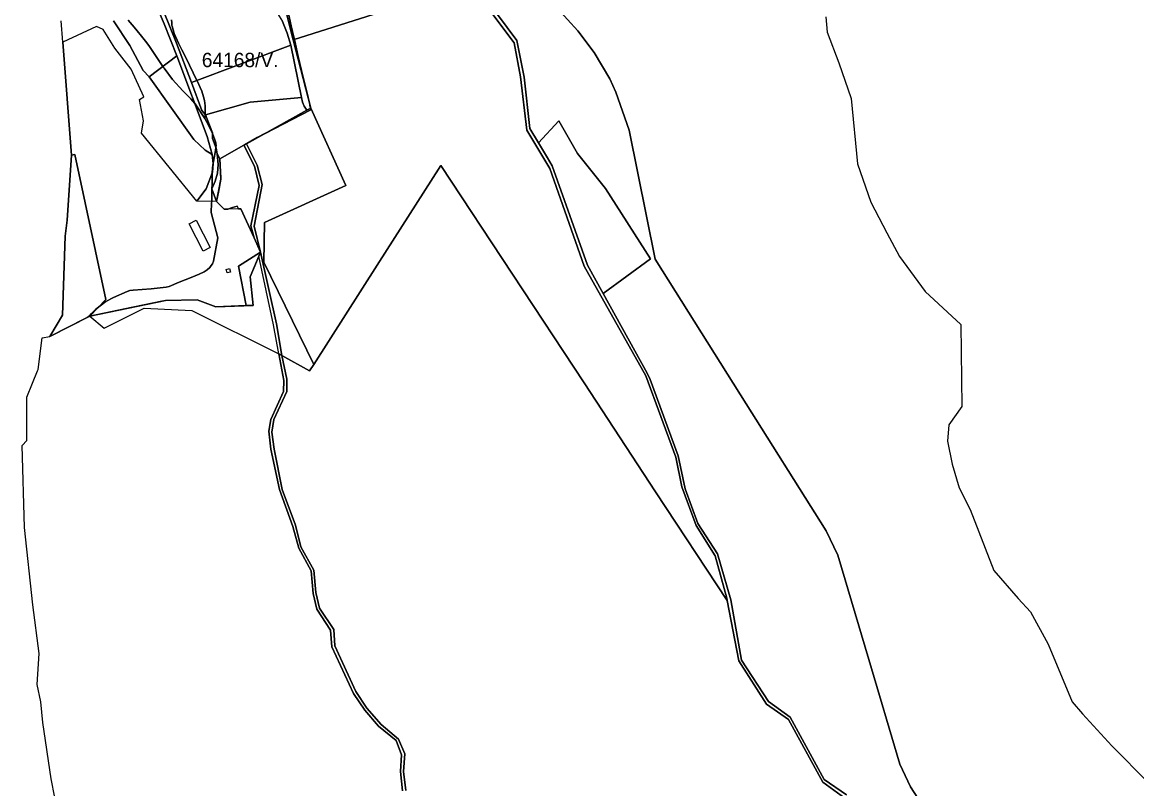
# Model space of a CAD drawing. Extents: x -521939 to -516426, y -1197857 to -1189551.
# Drawn here: x -518761 to -517594, y -1195785 to -1194982 of the extents above; entities that cross this region are included whole.
import ezdxf

# ---------------------------------------------------------------- set-up
doc = ezdxf.new("R2010")
doc.units = 0
for name, color, linetype in [('95610013', 7, 'Continuous'), ('95620013', 7, 'Continuous'), ('95640013', 7, 'Continuous'), ('95660013', 7, 'Continuous')]:
    doc.layers.add(name, color=color, linetype=linetype)

msp = doc.modelspace()

# ---------------------------------------------------------------- linework, layer by layer
at = {"layer": '95610013'}
for points in [[(-518612.73, -1194971.22), (-518551.19, -1194925.86), (-518520.66, -1194944.85), (-518503.52, -1194959.79), (-518495.28, -1194970.1), (-518488.5, -1194981.42), (-518483.3, -1194993.56), (-518479.79, -1195006.28), (-518583.67, -1195045.33), (-518599.24, -1195003.9)], [(-518479.79, -1195006.28), (-518468.55, -1195061.01), (-518522.17, -1195065.75), (-518568.86, -1195079.07), (-518572.72, -1195074.48), (-518583.67, -1195045.33)], [(-518599.15, -1195017.18), (-518567.19, -1195102), (-518561.85, -1195120.59), (-518569.49, -1195116.16), (-518581.19, -1195104.89), (-518627.9, -1195039.34)]]:
    msp.add_lwpolyline(points, close=True, dxfattribs=at)
for points in [[(-518664.08, -1195009.33), (-518676.07, -1194989.56), (-518683.25, -1194986.41), (-518718.38, -1195002.82)], [(-518718.38, -1195002.82), (-518709.39, -1195121.23)], [(-518638.26, -1195062.96), (-518633.66, -1195060.2), (-518646.72, -1195031.42), (-518664.08, -1195009.33)], [(-518633.95, -1195085.34), (-518638.26, -1195062.96)], [(-518636.1, -1195098.41), (-518633.95, -1195085.34)], [(-518577.92, -1195169.54), (-518636.1, -1195098.41)], [(-518709.39, -1195121.23), (-518705.84, -1195120.86)], [(-518705.84, -1195120.86), (-518673.48, -1195272.59), (-518690.03, -1195290)], [(-518557.33, -1195169.83), (-518577.92, -1195169.54)], [(-518518.2, -1195207.89), (-518532.16, -1195177.68), (-518549.4, -1195178.09), (-518557.33, -1195169.83)], [(-518578.9, -1195189.46), (-518563.97, -1195218.15), (-518571.3, -1195222), (-518586.21, -1195193.27)], [(-518586.21, -1195193.27), (-518578.9, -1195189.46)], [(-518511.27, -1195222.88), (-518518.2, -1195207.89)], [(-518534.54, -1195237.63), (-518511.27, -1195222.88)], [(-518547.43, -1195241.34), (-518543.93, -1195240.33), (-518542.94, -1195243.86), (-518546.46, -1195244.84)], [(-518546.46, -1195244.84), (-518547.43, -1195241.34)], [(-518526.44, -1195279.07), (-518534.54, -1195237.63)], [(-518690.03, -1195290), (-518610.94, -1195273.71), (-518577.83, -1195273)], [(-518577.83, -1195273), (-518558.14, -1195280.21), (-518526.44, -1195279.07)]]:
    msp.add_lwpolyline(points, dxfattribs=at)
at = {"layer": '95620013'}
for points in [[(-518477.04, -1195000.54), (-518484.79, -1194970.06), (-518513.79, -1194941.58), (-518572.38, -1194906.86), (-518586.43, -1194895.87), (-518625.17, -1194805.96), (-518626.13, -1194801.22), (-518615.19, -1194776.18), (-518588.67, -1194800), (-518568.59, -1194820.97), (-518540.54, -1194837.64), (-518520.62, -1194853.23), (-518507.34, -1194830.62), (-518479.49, -1194844.01), (-518465.35, -1194851.3), (-518442.17, -1194859), (-518428.24, -1194864.28), (-518400.82, -1194885.57), (-518302.06, -1194944.78)], [(-518511.27, -1195222.88), (-518518.19, -1195195.9), (-518509.49, -1195152.1), (-518514.93, -1195132.02), (-518526.18, -1195109.58), (-518462.79, -1195074.28), (-518458.85, -1195072.09), (-518422.19, -1195153.31), (-518507.32, -1195192.11), (-518507.9, -1195233.52), (-518455.62, -1195340.79), (-518459.94, -1195347.56), (-518489.13, -1195331.28), (-518494.68, -1195298.25)], [(-518169, -1195236.77), (-518205.88, -1195132.49), (-518210.84, -1195124.15), (-518220.27, -1195108.55), (-518198.96, -1195085.5), (-518179.28, -1195119.8), (-518150.08, -1195156.42), (-518103.1, -1195229.89), (-518152.55, -1195266.5)], [(-518549.4, -1195178.09), (-518557.33, -1195169.83), (-518553.05, -1195146.52), (-518553.98, -1195125.07), (-518528.8, -1195111.04), (-518517.78, -1195132.75), (-518512.67, -1195153.14), (-518521.52, -1195195.52), (-518518.2, -1195207.89), (-518532.16, -1195177.68)], [(-518492.07, -1195329.64), (-518497.86, -1195299.13), (-518513.12, -1195227.2), (-518511.27, -1195222.88), (-518494.68, -1195298.25), (-518489.13, -1195331.28)]]:
    msp.add_lwpolyline(points, close=True, dxfattribs=at)
for points in [[(-518277.38, -1194961.25), (-518245.58, -1195003.83), (-518239.05, -1195039.28), (-518232.28, -1195095.17), (-518208.33, -1195135.21), (-518172.54, -1195237.68), (-518107.85, -1195352.72), (-518076.29, -1195438.01), (-518070.24, -1195468.86), (-518055.13, -1195509.5), (-518035.17, -1195541.44), (-518022.96, -1195585.48), (-518022.49, -1195587.97), (-518097.53, -1195474.05), (-518172.57, -1195360.13), (-518247.61, -1195246.21), (-518322.65, -1195132.29), (-518389.14, -1195236.54), (-518455.62, -1195340.79), (-518507.9, -1195233.52), (-518507.32, -1195192.11), (-518422.19, -1195153.31), (-518458.85, -1195072.09), (-518477.04, -1195000.54), (-518302.06, -1194944.78)], [(-517897.53, -1195791.8), (-517920.87, -1195775.71), (-517956.78, -1195710.39), (-517979.28, -1195694.05), (-518007.69, -1195650.5), (-518018.82, -1195587.36), (-518032.6, -1195539.21), (-518053.4, -1195507.39), (-518066.46, -1195471.1), (-518073.84, -1195436.5), (-518103.22, -1195356.54), (-518106.36, -1195350), (-518152.55, -1195266.5), (-518103.1, -1195229.89), (-518150.08, -1195156.42), (-518179.28, -1195119.8), (-518198.96, -1195085.5), (-518220.27, -1195108.55), (-518229.34, -1195093.54), (-518235.27, -1195039.83), (-518242.88, -1195001.36), (-518274.2, -1194958.76)], [(-518200.55, -1194967.23), (-518179.17, -1194990.94), (-518161.76, -1195013.8), (-518145.64, -1195041.48), (-518139.37, -1195055.41), (-518125.34, -1195095.33), (-518098.11, -1195230.42), (-518008.6, -1195372.71), (-517919.1, -1195515.01), (-517906.62, -1195540.42), (-517874.16, -1195650.02), (-517841.71, -1195759.62), (-517830.56, -1195783.46), (-517733.42, -1195933.26), (-517671.34, -1196044.27), (-517550.36, -1196112.6)], [(-517550.36, -1196112.6), (-517671.34, -1196044.27), (-517733.42, -1195933.26), (-517830.56, -1195783.46), (-517841.71, -1195759.62), (-517874.16, -1195650.02), (-517906.62, -1195540.42), (-517919.1, -1195515.01), (-518008.6, -1195372.71), (-518098.11, -1195230.42), (-518125.34, -1195095.33), (-518139.37, -1195055.41), (-518145.64, -1195041.48), (-518161.76, -1195013.8), (-518179.17, -1194990.94), (-518200.55, -1194967.23)], [(-517919.16, -1194976.41), (-517918.02, -1194992.59), (-517905.77, -1195024.59), (-517892.85, -1195062.16), (-517886.13, -1195130.55), (-517872.07, -1195170.61), (-517855.27, -1195202.9), (-517841.99, -1195227.55), (-517815.27, -1195264.33), (-517777.74, -1195299), (-517776.69, -1195384.65), (-517790.61, -1195404.02), (-517791.97, -1195421.06), (-517786.92, -1195445.13), (-517779.75, -1195470.04), (-517768.13, -1195492.77), (-517743.18, -1195556.56), (-517718.01, -1195585.89), (-517705.09, -1195599.86), (-517686.33, -1195633.83), (-517661.21, -1195694.16), (-517650.43, -1195706.76), (-517619.7, -1195740.35), (-517580.93, -1195779.39)], [(-518709.39, -1195121.23), (-518713.87, -1195189.36)], [(-518690.03, -1195290), (-518673.48, -1195272.59), (-518705.84, -1195120.86), (-518709.39, -1195121.23)], [(-518359.34, -1195787.34), (-518361.52, -1195767.14), (-518360.06, -1195748.63), (-518366.96, -1195733.39), (-518384.97, -1195718.15), (-518400.09, -1195700.97), (-518411.58, -1195683.31), (-518433.46, -1195635.76), (-518434.43, -1195618.46), (-518449.55, -1195596.21), (-518453.54, -1195579.75), (-518455.59, -1195556.28), (-518469.14, -1195531.73), (-518474.58, -1195509.22), (-518488.85, -1195471.72), (-518497.07, -1195429.38), (-518499.49, -1195411.6), (-518497.55, -1195398.29), (-518483.65, -1195369.14), (-518483.89, -1195356.31), (-518489.13, -1195331.28), (-518459.94, -1195347.56), (-518455.62, -1195340.79), (-518389.14, -1195236.54), (-518322.65, -1195132.29), (-518247.61, -1195246.21), (-518172.57, -1195360.13), (-518097.53, -1195474.05), (-518022.49, -1195587.97), (-518010.51, -1195651.29), (-517981.36, -1195696.65), (-517958.51, -1195712.86), (-517922.6, -1195778.43), (-517899.26, -1195795.12)], [(-518713.87, -1195189.36), (-518716.08, -1195206.38)], [(-518716.08, -1195206.38), (-518718.82, -1195289.08)], [(-518511.27, -1195222.88), (-518534.54, -1195237.63), (-518526.44, -1195279.07)], [(-518513.12, -1195227.2), (-518511.27, -1195222.88)], [(-518522.38, -1195248.79), (-518513.12, -1195227.2)], [(-518513.12, -1195227.2), (-518522.38, -1195248.79)], [(-518497.86, -1195299.13), (-518513.12, -1195227.2)], [(-518526.44, -1195279.07), (-518519.2, -1195278.81), (-518522.38, -1195248.79)], [(-518522.38, -1195248.79), (-518519.2, -1195278.81), (-518526.44, -1195279.07)], [(-518726.63, -1195794.44), (-518730.8, -1195775.07), (-518739.22, -1195715.86), (-518741.37, -1195694.14), (-518745.32, -1195675.95), (-518743.14, -1195643.78), (-518749.83, -1195592.65), (-518758.62, -1195511.5), (-518760.89, -1195425.68), (-518755.96, -1195420.36), (-518756, -1195391.6), (-518756.03, -1195375.1), (-518750.12, -1195360.34), (-518744.97, -1195347.47), (-518744.35, -1195345.93), (-518740.14, -1195312.89), (-518731.97, -1195311.31), (-518690.03, -1195290), (-518675.19, -1195302.83), (-518633.33, -1195281.9), (-518583.48, -1195284.08), (-518492.07, -1195329.64), (-518487, -1195357.52), (-518487.48, -1195369.14), (-518500.47, -1195398.45), (-518502.61, -1195410.75), (-518500.64, -1195429.42), (-518491.66, -1195471.79), (-518477.5, -1195510.37), (-518471.35, -1195533.39), (-518458.29, -1195557.03), (-518456.21, -1195580.74), (-518452.41, -1195597.12), (-518437.97, -1195619.03), (-518436.59, -1195636.73), (-518414.13, -1195685.4), (-518402.18, -1195703.09), (-518387.88, -1195719.82), (-518369.43, -1195734.96), (-518363.62, -1195749.69), (-518364.73, -1195767.11), (-518362.66, -1195787.64)], [(-518526.44, -1195279.07), (-518558.14, -1195280.21), (-518577.83, -1195273), (-518610.94, -1195273.71), (-518690.03, -1195290)], [(-518690.03, -1195290), (-518675.19, -1195302.83), (-518633.33, -1195281.9)], [(-518633.33, -1195281.9), (-518583.48, -1195284.08), (-518492.07, -1195329.64)], [(-518718.82, -1195289.08), (-518731.97, -1195311.31)], [(-518731.97, -1195311.31), (-518690.03, -1195290)], [(-518492.07, -1195329.64), (-518497.86, -1195299.13)], [(-518362.66, -1195787.64), (-518364.73, -1195767.11), (-518363.62, -1195749.69), (-518369.43, -1195734.96), (-518387.88, -1195719.82), (-518402.18, -1195703.09), (-518414.13, -1195685.4), (-518436.59, -1195636.73), (-518437.97, -1195619.03), (-518452.41, -1195597.12), (-518456.21, -1195580.74), (-518458.29, -1195557.03), (-518471.35, -1195533.39), (-518477.5, -1195510.37), (-518491.66, -1195471.79), (-518500.64, -1195429.42), (-518502.61, -1195410.75), (-518500.47, -1195398.45), (-518487.48, -1195369.14), (-518487, -1195357.52), (-518492.07, -1195329.64), (-518489.13, -1195331.28), (-518483.89, -1195356.31), (-518483.65, -1195369.14), (-518497.55, -1195398.29), (-518499.49, -1195411.6), (-518497.07, -1195429.38), (-518488.85, -1195471.72), (-518474.58, -1195509.22), (-518469.14, -1195531.73), (-518455.59, -1195556.28), (-518453.54, -1195579.75), (-518449.55, -1195596.21), (-518434.43, -1195618.46), (-518433.46, -1195635.76), (-518411.58, -1195683.31), (-518400.09, -1195700.97), (-518384.97, -1195718.15), (-518366.96, -1195733.39), (-518360.06, -1195748.63), (-518361.52, -1195767.14), (-518359.34, -1195787.34)]]:
    msp.add_lwpolyline(points, dxfattribs=at)
at = {"layer": '95640013'}
for points in [[(-518621.14, -1194963.55), (-518612.46, -1194983.75), (-518599.15, -1195017.18), (-518627.9, -1195039.34), (-518634.25, -1195032.5), (-518648.26, -1195006.39), (-518665.42, -1194980.49)], [(-518612.73, -1194971.22), (-518599.24, -1195003.9), (-518583.67, -1195045.33), (-518572.72, -1195074.48), (-518568.86, -1195079.07), (-518561.77, -1195097.95), (-518561.65, -1195103.95), (-518557.91, -1195113.9), (-518556.68, -1195119.84), (-518555.66, -1195131.33), (-518556.55, -1195140.1), (-518558.78, -1195148.62), (-518562.28, -1195156.71), (-518557.33, -1195169.83), (-518577.92, -1195169.54), (-518568.34, -1195156.53), (-518561.84, -1195139.14), (-518560.97, -1195129.99), (-518561.85, -1195120.59), (-518567.19, -1195102), (-518599.15, -1195017.18), (-518612.46, -1194983.75), (-518621.14, -1194963.55)], [(-517899.26, -1195795.12), (-517922.6, -1195778.43), (-517958.51, -1195712.86), (-517981.36, -1195696.65), (-518010.51, -1195651.29), (-518022.49, -1195587.97), (-518022.96, -1195585.48), (-518035.17, -1195541.44), (-518055.13, -1195509.5), (-518070.24, -1195468.86), (-518076.29, -1195438.01), (-518107.85, -1195352.72), (-518172.54, -1195237.68), (-518208.33, -1195135.21), (-518232.28, -1195095.17), (-518239.05, -1195039.28), (-518245.58, -1195003.83), (-518277.38, -1194961.25)], [(-518274.2, -1194958.76), (-518242.88, -1195001.36), (-518235.27, -1195039.83), (-518229.34, -1195093.54), (-518220.27, -1195108.55), (-518210.84, -1195124.15), (-518205.88, -1195132.49), (-518169, -1195236.77), (-518152.55, -1195266.5), (-518106.36, -1195350), (-518103.22, -1195356.54), (-518073.84, -1195436.5), (-518066.46, -1195471.1), (-518053.4, -1195507.39), (-518032.6, -1195539.21), (-518018.82, -1195587.36), (-518007.69, -1195650.5), (-517979.28, -1195694.05), (-517956.78, -1195710.39), (-517920.87, -1195775.71), (-517897.53, -1195791.8)], [(-518484.79, -1194970.06), (-518477.04, -1195000.54), (-518458.85, -1195072.09), (-518462.79, -1195074.28), (-518463.67, -1195073.15), (-518465.57, -1195070.13), (-518467.43, -1195065.76), (-518468.55, -1195061.01), (-518479.79, -1195006.28), (-518483.3, -1194993.56), (-518488.5, -1194981.42)], [(-518665.42, -1194980.49), (-518648.26, -1195006.39), (-518634.25, -1195032.5), (-518627.9, -1195039.34), (-518581.19, -1195104.89), (-518569.49, -1195116.16), (-518561.85, -1195120.59), (-518560.97, -1195129.99), (-518561.84, -1195139.14), (-518568.34, -1195156.53), (-518577.92, -1195169.54), (-518636.1, -1195098.41), (-518633.95, -1195085.34), (-518638.26, -1195062.96), (-518633.66, -1195060.2), (-518646.72, -1195031.42), (-518664.08, -1195009.33), (-518676.07, -1194989.56), (-518683.25, -1194986.41), (-518718.38, -1195002.82), (-518720.07, -1194980.61)]]:
    msp.add_lwpolyline(points, dxfattribs=at)
for points in [[(-518556.68, -1195119.84), (-518557.91, -1195113.9), (-518561.65, -1195103.95), (-518561.77, -1195097.95), (-518568.86, -1195079.07), (-518522.17, -1195065.75), (-518468.55, -1195061.01), (-518467.43, -1195065.76), (-518465.57, -1195070.13), (-518463.67, -1195073.15), (-518462.79, -1195074.28), (-518526.18, -1195109.58), (-518528.8, -1195111.04), (-518553.98, -1195125.07)], [(-518518.19, -1195195.9), (-518511.27, -1195222.88), (-518518.2, -1195207.89), (-518521.52, -1195195.52), (-518512.67, -1195153.14), (-518517.78, -1195132.75), (-518528.8, -1195111.04), (-518526.18, -1195109.58), (-518514.93, -1195132.02), (-518509.49, -1195152.1)], [(-518557.33, -1195169.83), (-518562.28, -1195156.71), (-518558.78, -1195148.62), (-518556.55, -1195140.1), (-518555.66, -1195131.33), (-518556.68, -1195119.84), (-518553.98, -1195125.07), (-518553.05, -1195146.52)], [(-518586.21, -1195193.27), (-518578.9, -1195189.46), (-518563.97, -1195218.15), (-518571.3, -1195222)], [(-518547.43, -1195241.34), (-518543.93, -1195240.33), (-518542.94, -1195243.86), (-518546.46, -1195244.84)]]:
    msp.add_lwpolyline(points, close=True, dxfattribs=at)
at = {"layer": '95660013'}
for points in [[(-518726.63, -1195794.44), (-518730.8, -1195775.07), (-518739.22, -1195715.86), (-518741.37, -1195694.14), (-518745.32, -1195675.95), (-518743.14, -1195643.78), (-518749.83, -1195592.65), (-518758.62, -1195511.5), (-518760.89, -1195425.68), (-518755.96, -1195420.36), (-518756, -1195391.6), (-518756.03, -1195375.1), (-518750.12, -1195360.34), (-518744.97, -1195347.47), (-518744.35, -1195345.93), (-518740.14, -1195312.89), (-518731.97, -1195311.31), (-518695.18, -1195292.62), (-518691.72, -1195290.85), (-518690.03, -1195290), (-518645.23, -1195280.77), (-518614.73, -1195274.49), (-518610.94, -1195273.71), (-518577.83, -1195273), (-518558.14, -1195280.21), (-518519.2, -1195278.81), (-518522.38, -1195248.79), (-518515.66, -1195233.12), (-518513.12, -1195227.2), (-518511.27, -1195222.88), (-518518.2, -1195207.89), (-518532.16, -1195177.68), (-518533.68, -1195177.72), (-518534.57, -1195177.74), (-518535.23, -1195176.3), (-518535.87, -1195174.93), (-518540.57, -1195176.4), (-518545.69, -1195178), (-518549.4, -1195178.09), (-518555.98, -1195171.24), (-518557.33, -1195169.83), (-518555.55, -1195160.16), (-518553.05, -1195146.52), (-518553.09, -1195145.55), (-518553.98, -1195125.07), (-518548.49, -1195122.01), (-518528.8, -1195111.05), (-518528.19, -1195110.71), (-518514.85, -1195102.93), (-518506.77, -1195098.77), (-518506.65, -1195098.71), (-518458.58, -1195074), (-518458.93, -1195072.33), (-518458.99, -1195072.16), (-518459.59, -1195069.18), (-518459.61, -1195069.08), (-518459.86, -1195067.9), (-518461.32, -1195060.85), (-518464.87, -1195046.81), (-518468.49, -1195032.5), (-518471.79, -1195018.01), (-518475.85, -1195000.16), (-518476.08, -1194999.14), (-518479.17, -1194986.02), (-518482.78, -1194969.81)], [(-518482.78, -1194969.81), (-518479.17, -1194986.02), (-518476.08, -1194999.14), (-518475.85, -1195000.16), (-518471.79, -1195018.01), (-518468.49, -1195032.5), (-518464.87, -1195046.81), (-518461.32, -1195060.85), (-518459.86, -1195067.9), (-518459.61, -1195069.08), (-518459.59, -1195069.18), (-518458.99, -1195072.16), (-518458.93, -1195072.33), (-518458.58, -1195074), (-518506.65, -1195098.71), (-518506.77, -1195098.77), (-518514.85, -1195102.93), (-518528.19, -1195110.71), (-518528.8, -1195111.05), (-518548.49, -1195122.01), (-518553.98, -1195125.07), (-518553.09, -1195145.55), (-518553.05, -1195146.52), (-518555.55, -1195160.16), (-518557.33, -1195169.83), (-518555.98, -1195171.24), (-518549.4, -1195178.09), (-518545.69, -1195178), (-518540.57, -1195176.4), (-518535.87, -1195174.93), (-518535.23, -1195176.3), (-518534.57, -1195177.74), (-518533.68, -1195177.72), (-518532.16, -1195177.68), (-518518.2, -1195207.89), (-518511.27, -1195222.88), (-518513.12, -1195227.2), (-518515.66, -1195233.12), (-518522.38, -1195248.79), (-518519.2, -1195278.81), (-518558.14, -1195280.21), (-518577.83, -1195273), (-518610.94, -1195273.71), (-518614.73, -1195274.49), (-518645.23, -1195280.77), (-518690.03, -1195290), (-518691.72, -1195290.85), (-518690.42, -1195289.61), (-518688.29, -1195287.34), (-518683.88, -1195282.63), (-518673.56, -1195274.6), (-518665.28, -1195270.4), (-518651.05, -1195264.34), (-518648.25, -1195263.29), (-518644.87, -1195262.71), (-518625.74, -1195261.31), (-518610.23, -1195259.56), (-518606.96, -1195258.97), (-518596.42, -1195254.64), (-518583.98, -1195249.53), (-518575.6, -1195246.02), (-518570.34, -1195243.81), (-518567.42, -1195241.42), (-518564.5, -1195239.03), (-518562.98, -1195237.14), (-518561.59, -1195235.41), (-518560.54, -1195232.38), (-518555.99, -1195208), (-518562.99, -1195181.52), (-518562.61, -1195171.84), (-518562.53, -1195169.76), (-518562.52, -1195169.39), (-518562.26, -1195156.73), (-518562.17, -1195152.31), (-518561.9, -1195139.26), (-518561.82, -1195135.69), (-518561.72, -1195135.12), (-518561.15, -1195131.85), (-518558.44, -1195116.41), (-518558.14, -1195113.29), (-518557.91, -1195110.87), (-518558.09, -1195109.5), (-518558.26, -1195108.39), (-518559.14, -1195105.33), (-518561.75, -1195098.76), (-518562.7, -1195096.38), (-518565.42, -1195090.84), (-518566.25, -1195089.15), (-518569.64, -1195083.08), (-518569.52, -1195078.29), (-518569.46, -1195076.02), (-518569.23, -1195069.81), (-518570.16, -1195063.98), (-518570.98, -1195060.13), (-518572.73, -1195054.42), (-518577.74, -1195043.57), (-518577.93, -1195043.17), (-518589.76, -1195018.96), (-518593.81, -1195011.05), (-518597.45, -1195003.94), (-518601.77, -1194993.79), (-518603.85, -1194986.29), (-518604.1, -1194985.39), (-518604.36, -1194982.73), (-518604.69, -1194979.45)], [(-517919.16, -1194976.41), (-517918.02, -1194992.59), (-517905.77, -1195024.59), (-517892.85, -1195062.16), (-517886.13, -1195130.55), (-517872.07, -1195170.61), (-517855.27, -1195202.9), (-517841.99, -1195227.55), (-517815.27, -1195264.33), (-517777.74, -1195299), (-517776.69, -1195384.65), (-517790.61, -1195404.02), (-517791.97, -1195421.06), (-517786.92, -1195445.13), (-517779.75, -1195470.04), (-517768.13, -1195492.77), (-517743.18, -1195556.56), (-517718.01, -1195585.89), (-517705.09, -1195599.86), (-517686.33, -1195633.83), (-517661.21, -1195694.16), (-517650.43, -1195706.76), (-517619.7, -1195740.35), (-517580.93, -1195779.39)], [(-518649.83, -1194980.06), (-518643.64, -1194987.35), (-518640.5, -1194991.16), (-518635.89, -1194996.74), (-518631.97, -1195001.95), (-518628.48, -1195006.59), (-518613.72, -1195028.41), (-518612.85, -1195029.69), (-518612.39, -1195030.31), (-518603.52, -1195042.17), (-518592.67, -1195053.98), (-518584.39, -1195062.44), (-518580.3, -1195067.22), (-518579.9, -1195067.68), (-518569.64, -1195083.08), (-518566.25, -1195089.15), (-518565.42, -1195090.84), (-518562.7, -1195096.38), (-518561.75, -1195098.76), (-518559.14, -1195105.33), (-518558.26, -1195108.39), (-518558.09, -1195109.5), (-518557.91, -1195110.87), (-518558.14, -1195113.29), (-518558.44, -1195116.41), (-518561.15, -1195131.85), (-518561.72, -1195135.12), (-518561.82, -1195135.69), (-518561.9, -1195139.26), (-518562.17, -1195152.31), (-518562.26, -1195156.73), (-518562.52, -1195169.39), (-518562.53, -1195169.76), (-518562.61, -1195171.84), (-518562.99, -1195181.52), (-518555.99, -1195208), (-518560.54, -1195232.38), (-518561.59, -1195235.41), (-518562.98, -1195237.14), (-518564.5, -1195239.03), (-518567.42, -1195241.42), (-518570.34, -1195243.81), (-518575.6, -1195246.02), (-518583.98, -1195249.53), (-518596.42, -1195254.64), (-518606.96, -1195258.97), (-518610.23, -1195259.56), (-518625.74, -1195261.31), (-518644.87, -1195262.71), (-518648.25, -1195263.29), (-518651.05, -1195264.34), (-518665.28, -1195270.4), (-518673.56, -1195274.6), (-518683.88, -1195282.63), (-518688.29, -1195287.34), (-518690.42, -1195289.61), (-518691.72, -1195290.85), (-518695.18, -1195292.62), (-518731.97, -1195311.31), (-518718.82, -1195289.08), (-518716.08, -1195206.38), (-518713.87, -1195189.36), (-518709.39, -1195121.23), (-518718.38, -1195002.82), (-518720.07, -1194980.61)], [(-518604.69, -1194979.45), (-518604.36, -1194982.73), (-518604.1, -1194985.39), (-518603.85, -1194986.29), (-518601.77, -1194993.79), (-518597.45, -1195003.94), (-518593.81, -1195011.05), (-518589.76, -1195018.96), (-518577.93, -1195043.17), (-518577.74, -1195043.57), (-518572.73, -1195054.42), (-518570.98, -1195060.13), (-518570.16, -1195063.98), (-518569.23, -1195069.81), (-518569.46, -1195076.02), (-518569.52, -1195078.29), (-518569.64, -1195083.08), (-518579.9, -1195067.68), (-518580.3, -1195067.22), (-518584.39, -1195062.44), (-518592.67, -1195053.98), (-518603.52, -1195042.17), (-518612.39, -1195030.31), (-518612.85, -1195029.69), (-518613.72, -1195028.41), (-518628.48, -1195006.59), (-518631.97, -1195001.95), (-518635.89, -1194996.74), (-518640.5, -1194991.16), (-518643.64, -1194987.35), (-518649.83, -1194980.06)]]:
    msp.add_lwpolyline(points, dxfattribs=at)

# ---------------------------------------------------------------- texts
msp.add_text('64168/V.', height=15, rotation=360, dxfattribs=at).set_placement((-518572.87, -1195029.15))

doc.saveas('drawing.dxf')
